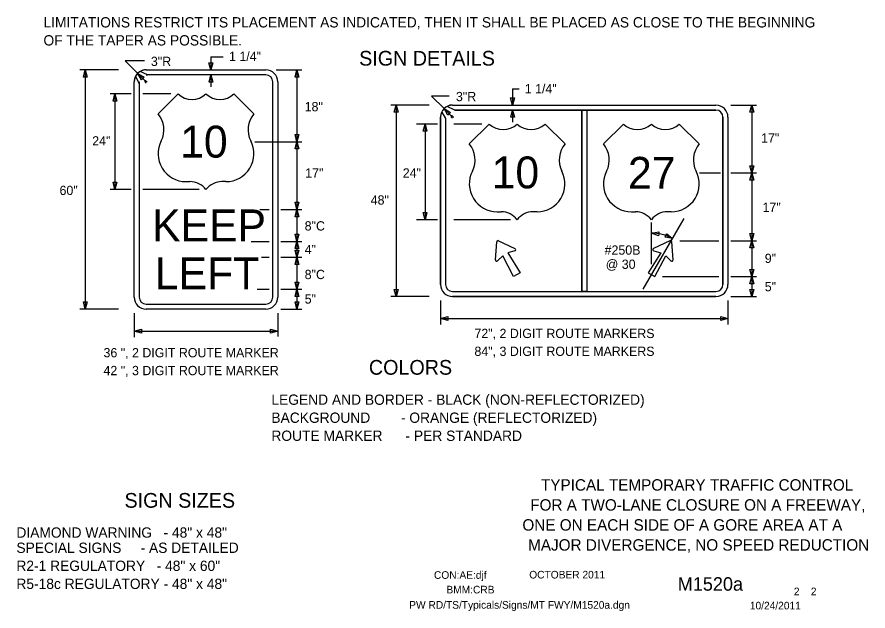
# Model space of a CAD drawing. Extents: x 16731 to 18475, y 7005 to 8303.
# Drawn here: x 17780 to 18473, y 7218 to 7702 of the extents above; entities that cross this region are included whole.
import ezdxf

# ---------------------------------------------------------------- set-up
doc = ezdxf.new("R2010")
doc.units = 0
for name, color, linetype in [('BORDER', 7, 'Continuous'), ('BORDER_SIGNAL_WO', 7, 'Continuous'), ('TRAFFIC_SIGNS_PR', 7, 'Continuous'), ('TYPICAL_EX', 7, 'Continuous'), ('TYPICAL_TEXT_DIMEN_PR', 7, 'Continuous')]:
    doc.layers.add(name, color=color, linetype=linetype)

msp = doc.modelspace()

# ---------------------------------------------------------------- linework, layer by layer
at = {"layer": 'BORDER'}
msp.add_line((17909.25, 7314.23), (17909.25, 7314.23), dxfattribs=at)
at = {"layer": 'TRAFFIC_SIGNS_PR'}
for p, q in [((17886.5, 7654.99), (17880.4, 7657.74)), ((17885.3, 7659.06), (17982.8, 7659.06)), ((17877.72, 7655.44), (17876.71, 7653.93)), ((17876.74, 7653.86), (17879.61, 7647.82)), ((17982.8, 7654.99), (17885.3, 7654.99)), ((17875.55, 7473.81), (17875.55, 7649.31)), ((17879.61, 7649.31), (17879.61, 7473.81)), ((17988.48, 7473.81), (17988.48, 7649.31)), ((17992.55, 7649.31), (17992.55, 7473.81)), ((18134.82, 7630.36), (18349.32, 7630.36)), ((18134.82, 7630.36), (18349.32, 7630.36)), ((18125.99, 7624.62), (18129.12, 7619.57)), ((18136.77, 7626.31), (18130.54, 7629.32)), ((18136.76, 7626.3), (18240.04, 7626.3)), ((18349.32, 7626.3), (18136.76, 7626.3)), ((18240.04, 7626.3), (18240.04, 7478.42)), ((18244.1, 7626.3), (18244.1, 7478.42)), ((18244.1, 7626.3), (18349.32, 7626.3)), ((18125.07, 7620.61), (18125.07, 7484.11)), ((18125.07, 7484.11), (18125.07, 7620.61)), ((18129.13, 7619.56), (18129.13, 7484.11)), ((18129.13, 7619.56), (18129.13, 7484.11)), ((18355.01, 7620.61), (18355.01, 7574.86)), ((18355.01, 7484.11), (18355.01, 7620.61)), ((18359.07, 7620.61), (18359.07, 7484.11)), ((18359.07, 7620.61), (18359.07, 7484.11)), ((18355.01, 7574.86), (18355.01, 7484.11)), ((18169.67, 7504.22), (18170.82, 7518.93)), ((18172.33, 7519.8), (18185.65, 7513.44)), ((18311.8, 7519.8), (18298.49, 7513.44)), ((18314.47, 7504.22), (18313.31, 7518.93)), ((18134.82, 7478.42), (18349.32, 7478.42)), ((18134.82, 7474.36), (18349.32, 7474.36)), ((18349.32, 7474.36), (18134.82, 7474.36)), ((17885.3, 7468.12), (17982.8, 7468.12)), ((17982.8, 7464.06), (17885.3, 7464.06))]:
    msp.add_line(p, q, dxfattribs=at)
for points in [[(18136.76, 7626.3), (18136.74, 7626.3)], [(18129.12, 7619.57), (18129.13, 7619.56)], [(18185.49, 7511.47), (18179.76, 7509.9), (18189.98, 7493.73), (18184.58, 7490.61), (18175.69, 7507.54), (18171.46, 7503.38)], [(18298.65, 7511.47), (18304.37, 7509.9), (18294.16, 7493.73), (18299.55, 7490.61), (18308.45, 7507.54), (18312.67, 7503.38)]]:
    msp.add_lwpolyline(points, dxfattribs=at)
msp.add_lwpolyline([(18240.04, 7626.3), (18244.1, 7626.3), (18244.1, 7478.42), (18240.04, 7478.42)], close=True, dxfattribs=at)
for centre, radius, start, end in [((17885.3, 7649.31), 9.75, 90, 180), ((17884.71, 7651.48), 7.6, 85.58319, 124.53531), ((17982.8, 7649.31), 9.75, 0, 90), ((17882.58, 7649.9), 7.06, 145.86811, 184.82317), ((17885.9, 7659.42), 4.47, 262.2432, 277.7568), ((17982.8, 7649.31), 5.69, 0, 90), ((17874.15, 7648.56), 5.51, 352.24294, 7.75653), ((18134.82, 7620.61), 9.75, 90, 180), ((18134.82, 7620.61), 9.75, 90, 180), ((18134.14, 7623.79), 6.6, 84.11162, 123.06374), ((18349.32, 7620.61), 9.75, 0, 90), ((18349.32, 7620.61), 9.75, 0, 90), ((18131.2, 7621.31), 6.17, 147.60925, 186.56283), ((18135.76, 7633.48), 7.24, 277.81035, 278.05403), ((18349.32, 7620.61), 5.69, 0, 89.99421), ((18349.32, 7620.61), 5.69, 0, 90), ((18171.88, 7518.85), 1.06, 64.48226, 175.51774), ((18312.26, 7518.85), 1.06, 4.48226, 115.51774), ((18185.19, 7512.49), 1.06, 285.9885, 64.48226), ((18298.94, 7512.49), 1.06, 115.51774, 254.0115), ((18170.73, 7504.14), 1.06, 175.51775, 314.01151), ((18313.41, 7504.14), 1.06, 225.98849, 4.48225), ((18134.82, 7484.11), 9.75, 180, 270), ((18134.82, 7484.11), 9.75, 180, 270), ((18134.82, 7484.11), 5.69, 180, 270), ((18134.82, 7484.11), 5.69, 180, 270), ((18349.32, 7484.11), 9.75, 270, 0), ((18349.32, 7484.11), 5.69, 270, 0), ((18349.32, 7484.11), 9.75, 270, 0), ((18349.32, 7484.11), 5.69, 270, 0), ((17885.3, 7473.81), 9.75, 180, 270), ((17885.3, 7473.81), 5.69, 180, 270), ((17982.8, 7473.81), 5.69, 270, 0), ((17982.8, 7473.81), 9.75, 270, 0)]:
    msp.add_arc(centre, radius, start, end, dxfattribs=at)
at = {"layer": 'TYPICAL_EX'}
for p, q in [((17895.05, 7623.31), (17911.3, 7639.56)), ((17973.05, 7623.31), (17956.8, 7639.56)), ((18148.43, 7598.7), (18164.68, 7614.95)), ((18226.43, 7598.7), (18210.18, 7614.95)), ((18257.71, 7598.7), (18273.96, 7614.95)), ((18335.71, 7598.7), (18319.46, 7614.95)), ((17917.77, 7568.02), (17921.02, 7568.02)), ((17950.32, 7568.02), (17947.07, 7568.02)), ((18171.16, 7543.41), (18174.41, 7543.41)), ((18203.7, 7543.41), (18200.45, 7543.41)), ((18280.43, 7543.41), (18283.68, 7543.41)), ((18312.98, 7543.41), (18309.73, 7543.41))]:
    msp.add_line(p, q, dxfattribs=at)
for centre, radius, start, end in [((17922.67, 7651.39), 16.42, 226.14041, 313.85958), ((17945.42, 7651.39), 16.42, 226.14042, 313.85959), ((17879.65, 7610.29), 20.16, 333.09768, 40.19361), ((17988.45, 7610.29), 20.16, 139.80639, 206.90233), ((18176.06, 7626.78), 16.42, 226.14041, 313.85958), ((18198.8, 7626.78), 16.42, 226.14042, 313.85959), ((18285.33, 7626.78), 16.42, 226.14041, 313.85958), ((18308.08, 7626.78), 16.42, 226.14042, 313.85959), ((17917.81, 7590.74), 22.73, 152.6698, 269.90132), ((17950.28, 7590.74), 22.73, 270.09868, 27.3302), ((18133.03, 7585.68), 20.16, 333.09768, 40.19361), ((18241.83, 7585.68), 20.16, 139.80639, 206.90233), ((18242.31, 7585.68), 20.16, 333.09768, 40.19361), ((18351.11, 7585.68), 20.16, 139.80639, 206.90233), ((18171.2, 7566.13), 22.73, 152.6698, 269.90132), ((18203.66, 7566.13), 22.73, 270.09868, 27.3302), ((18280.48, 7566.13), 22.73, 152.6698, 269.90132), ((18312.94, 7566.13), 22.73, 270.09868, 27.3302), ((17921.06, 7551.74), 16.28, 37.1038, 90.13853), ((17947.03, 7551.74), 16.28, 89.86147, 142.8962), ((18174.45, 7527.13), 16.28, 37.1038, 90.13853), ((18200.41, 7527.13), 16.28, 89.86147, 142.8962), ((18283.73, 7527.13), 16.28, 37.1038, 90.13853), ((18309.69, 7527.13), 16.28, 89.86147, 142.8962)]:
    msp.add_arc(centre, radius, start, end, dxfattribs=at)
at = {"layer": 'TYPICAL_TEXT_DIMEN_PR'}
for p, q in [((17883.92, 7666.34), (17868.26, 7666.34)), ((17868.26, 7666.34), (17878.5, 7656.1)), ((17938.02, 7659.06), (17936.45, 7664.92)), ((17936.45, 7664.92), (17938.02, 7664.92)), ((17938.02, 7669.82), (17938.02, 7659.06)), ((17938.02, 7669.82), (17948.12, 7669.82)), ((17938.02, 7664.92), (17939.59, 7664.92)), ((17939.59, 7664.92), (17938.02, 7659.06)), ((17862.72, 7659.06), (17831.42, 7659.06)), ((17834.19, 7653.19), (17835.76, 7659.06)), ((17835.76, 7659.06), (17835.76, 7464.06)), ((17835.76, 7659.06), (17837.33, 7653.19)), ((17991.09, 7659.06), (18012.05, 7659.06)), ((18006.58, 7653.19), (18008.15, 7659.06)), ((18008.15, 7659.06), (18008.15, 7600.56)), ((18008.15, 7659.06), (18009.72, 7653.19)), ((17835.76, 7653.19), (17834.19, 7653.19)), ((17837.33, 7653.19), (17835.76, 7653.19)), ((17878.5, 7656.1), (17885.06, 7649.55)), ((17881.53, 7650.85), (17878.5, 7656.1)), ((17878.5, 7656.1), (17883.75, 7653.07)), ((17882.64, 7651.96), (17881.53, 7650.85)), ((17883.75, 7653.07), (17882.64, 7651.96)), ((17885.06, 7648.34), (17885.06, 7650.76)), ((17936.5, 7649.13), (17938.07, 7654.99)), ((17938.07, 7654.99), (17938.07, 7645.24)), ((17938.07, 7654.99), (17939.64, 7649.13)), ((18008.15, 7653.19), (18006.58, 7653.19)), ((18009.72, 7653.19), (18008.15, 7653.19)), ((17883.85, 7649.55), (17886.26, 7649.55)), ((17938.07, 7649.13), (17936.5, 7649.13)), ((17939.64, 7649.13), (17938.07, 7649.13)), ((18183.67, 7643.51), (18183.67, 7630.36)), ((18183.67, 7643.51), (18189.2, 7643.51)), ((17873.17, 7639.56), (17856.05, 7639.56)), ((17858.37, 7633.69), (17859.94, 7639.56)), ((17859.94, 7639.56), (17859.94, 7561.56)), ((17859.94, 7639.56), (17861.51, 7633.69)), ((17905.41, 7639.56), (17882.54, 7639.56)), ((18131.96, 7637.64), (18117.78, 7637.64)), ((18117.78, 7637.64), (18127.93, 7627.49)), ((17859.94, 7633.69), (17858.37, 7633.69)), ((17861.51, 7633.69), (17859.94, 7633.69)), ((18115.83, 7630.36), (18084.54, 7630.36)), ((18087.31, 7624.5), (18088.88, 7630.36)), ((18088.88, 7630.36), (18088.88, 7474.36)), ((18088.88, 7630.36), (18090.45, 7624.5)), ((18183.68, 7630.36), (18182.1, 7636.22)), ((18182.1, 7636.22), (18183.68, 7636.22)), ((18183.68, 7636.22), (18185.25, 7636.22)), ((18185.25, 7636.22), (18183.68, 7630.36)), ((18361.44, 7630.36), (18382.4, 7630.36)), ((18376.93, 7624.5), (18378.5, 7630.36)), ((18378.5, 7630.36), (18378.5, 7575.11)), ((18378.5, 7630.36), (18380.08, 7624.5)), ((18088.88, 7624.5), (18087.31, 7624.5)), ((18090.45, 7624.5), (18088.88, 7624.5)), ((18127.93, 7627.49), (18134.58, 7620.85)), ((18130.97, 7622.24), (18127.93, 7627.49)), ((18127.93, 7627.49), (18133.19, 7624.46)), ((18132.08, 7623.35), (18130.97, 7622.24)), ((18133.19, 7624.46), (18132.08, 7623.35)), ((18182.15, 7620.43), (18183.73, 7626.3)), ((18182.15, 7620.43), (18183.73, 7626.3)), ((18183.72, 7626.3), (18183.72, 7616.55)), ((18183.73, 7626.3), (18185.3, 7620.43)), ((18183.73, 7626.3), (18185.3, 7620.43)), ((18378.5, 7624.5), (18376.93, 7624.5)), ((18380.08, 7624.5), (18378.5, 7624.5)), ((18133.37, 7620.85), (18135.79, 7620.85)), ((18134.58, 7619.64), (18134.58, 7622.06)), ((18183.73, 7620.43), (18182.15, 7620.43)), ((18183.73, 7620.43), (18182.15, 7620.43)), ((18185.3, 7620.43), (18183.73, 7620.43)), ((18185.3, 7620.43), (18183.73, 7620.43)), ((18122.69, 7614.95), (18105.57, 7614.95)), ((18110.87, 7609.08), (18112.44, 7614.95)), ((18112.44, 7609.08), (18110.87, 7609.08)), ((18112.44, 7614.95), (18112.44, 7536.95)), ((18112.44, 7614.95), (18114.01, 7609.08)), ((18114.01, 7609.08), (18112.44, 7609.08)), ((18158.8, 7614.95), (18135.92, 7614.95)), ((18008.15, 7600.56), (18006.58, 7606.42)), ((18006.58, 7606.42), (18008.15, 7606.42)), ((18008.15, 7606.42), (18009.72, 7606.42)), ((18009.72, 7606.42), (18008.15, 7600.56)), ((17973.94, 7600.56), (18012.05, 7600.56)), ((18006.58, 7594.69), (18008.15, 7600.56)), ((18008.15, 7600.56), (18008.15, 7545.31)), ((18008.15, 7600.56), (18009.72, 7594.69)), ((18008.15, 7594.69), (18006.58, 7594.69)), ((18009.72, 7594.69), (18008.15, 7594.69)), ((18378.5, 7575.11), (18376.93, 7580.97)), ((18376.93, 7580.97), (18378.5, 7580.97)), ((18378.5, 7580.97), (18380.08, 7580.97)), ((18380.08, 7580.97), (18378.5, 7575.11)), ((18335.88, 7575.11), (18353.03, 7575.11)), ((18361.44, 7575.11), (18382.4, 7575.11)), ((18376.93, 7569.25), (18378.5, 7575.11)), ((18378.5, 7575.11), (18378.5, 7519.86)), ((18378.5, 7575.11), (18380.08, 7569.25)), ((17859.94, 7561.56), (17858.37, 7567.42)), ((17858.37, 7567.42), (17859.94, 7567.42)), ((17859.94, 7567.42), (17861.51, 7567.42)), ((17861.51, 7567.42), (17859.94, 7561.56)), ((18378.5, 7569.25), (18376.93, 7569.25)), ((18380.08, 7569.25), (18378.5, 7569.25)), ((17873.17, 7561.56), (17856.05, 7561.56)), ((17928.54, 7561.56), (17882.54, 7561.56)), ((18008.15, 7545.31), (18006.58, 7551.17)), ((18006.58, 7551.17), (18008.15, 7551.17)), ((18008.15, 7551.17), (18009.72, 7551.17)), ((18009.72, 7551.17), (18008.15, 7545.31)), ((17977.88, 7545.31), (17985.56, 7545.31)), ((17994.92, 7545.31), (18012.05, 7545.31)), ((18006.58, 7539.44), (18008.15, 7545.31)), ((18008.15, 7539.44), (18006.58, 7539.44)), ((18008.15, 7545.31), (18008.15, 7519.31)), ((18008.15, 7545.31), (18009.72, 7539.44)), ((18009.72, 7539.44), (18008.15, 7539.44)), ((18112.44, 7536.95), (18110.87, 7542.81)), ((18110.87, 7542.81), (18112.44, 7542.81)), ((18112.44, 7542.81), (18114.01, 7542.81)), ((18114.01, 7542.81), (18112.44, 7536.95)), ((18122.69, 7536.95), (18105.57, 7536.95)), ((18181.92, 7536.95), (18135.92, 7536.95)), ((18290.1, 7480.46), (18323.34, 7538.05)), ((18296.86, 7500.61), (18296.86, 7534.6)), ((18296.89, 7526.05), (18302.88, 7527.01)), ((18302.56, 7523.89), (18296.89, 7526.05)), ((18302.88, 7527.01), (18302.72, 7525.45)), ((18308.56, 7524.14), (18309.24, 7525.56)), ((18309.24, 7525.56), (18313.84, 7521.6)), ((18378.5, 7519.86), (18376.93, 7525.72)), ((18376.93, 7525.72), (18378.5, 7525.72)), ((18378.5, 7525.72), (18380.08, 7525.72)), ((18380.08, 7525.72), (18378.5, 7519.86)), ((17970.86, 7519.31), (17985.56, 7519.31)), ((17994.92, 7519.31), (18012.05, 7519.31)), ((18008.15, 7519.31), (18006.58, 7525.17)), ((18006.58, 7525.17), (18008.15, 7525.17)), ((18006.58, 7513.44), (18008.15, 7519.31)), ((18008.15, 7525.17), (18009.72, 7525.17)), ((18009.72, 7525.17), (18008.15, 7519.31)), ((18008.15, 7519.31), (18008.15, 7506.31)), ((18008.15, 7519.31), (18009.72, 7513.44)), ((18302.72, 7525.45), (18302.56, 7523.89)), ((18307.87, 7522.73), (18308.56, 7524.14)), ((18313.84, 7521.6), (18307.87, 7522.73)), ((18319.81, 7519.86), (18351.68, 7519.86)), ((18361.44, 7519.86), (18382.4, 7519.86)), ((18376.93, 7514), (18378.5, 7519.86)), ((18378.5, 7519.86), (18378.5, 7490.61)), ((18378.5, 7519.86), (18380.08, 7514)), ((18008.15, 7513.44), (18006.58, 7513.44)), ((18008.15, 7506.31), (18006.58, 7512.17)), ((18006.58, 7512.17), (18008.15, 7512.17)), ((18009.72, 7513.44), (18008.15, 7513.44)), ((18008.15, 7512.17), (18009.72, 7512.17)), ((18009.72, 7512.17), (18008.15, 7506.31)), ((18378.5, 7514), (18376.93, 7514)), ((18380.08, 7514), (18378.5, 7514)), ((17979.21, 7506.31), (17985.56, 7506.31)), ((17994.92, 7506.31), (18012.05, 7506.31)), ((18006.58, 7500.44), (18008.15, 7506.31)), ((18008.15, 7506.31), (18008.15, 7480.31)), ((18008.15, 7506.31), (18009.72, 7500.44)), ((18008.15, 7500.44), (18006.58, 7500.44)), ((18009.72, 7500.44), (18008.15, 7500.44)), ((18378.5, 7490.61), (18376.93, 7496.47)), ((18376.93, 7496.47), (18378.5, 7496.47)), ((18378.5, 7496.47), (18380.08, 7496.47)), ((18380.08, 7496.47), (18378.5, 7490.61)), ((18008.15, 7480.31), (18006.58, 7486.17)), ((18006.58, 7486.17), (18008.15, 7486.17)), ((18008.15, 7486.17), (18009.72, 7486.17)), ((18009.72, 7486.17), (18008.15, 7480.31)), ((18305.67, 7490.61), (18351.68, 7490.61)), ((18361.44, 7490.61), (18382.4, 7490.61)), ((18376.93, 7484.75), (18378.5, 7490.61)), ((18378.5, 7484.75), (18376.93, 7484.75)), ((18378.5, 7490.61), (18378.5, 7474.36)), ((18378.5, 7490.61), (18380.08, 7484.75)), ((18380.08, 7484.75), (18378.5, 7484.75)), ((17975.71, 7480.31), (17985.56, 7480.31)), ((17994.92, 7480.31), (18012.05, 7480.31)), ((18006.58, 7474.44), (18008.15, 7480.31)), ((18008.15, 7480.31), (18008.15, 7464.06)), ((18008.15, 7480.31), (18009.72, 7474.44)), ((18088.88, 7474.36), (18087.31, 7480.22)), ((18087.31, 7480.22), (18088.88, 7480.22)), ((18088.88, 7480.22), (18090.45, 7480.22)), ((18090.45, 7480.22), (18088.88, 7474.36)), ((18378.5, 7474.36), (18376.93, 7480.22)), ((18376.93, 7480.22), (18378.5, 7480.22)), ((18378.5, 7480.22), (18380.08, 7480.22)), ((18380.08, 7480.22), (18378.5, 7474.36)), ((18008.15, 7474.44), (18006.58, 7474.44)), ((18009.72, 7474.44), (18008.15, 7474.44)), ((18115.83, 7474.36), (18084.54, 7474.36)), ((18125.07, 7471.01), (18125.07, 7451.45)), ((18359.07, 7471.01), (18359.07, 7451.45)), ((18361.44, 7474.36), (18378.57, 7474.36)), ((18361.44, 7474.36), (18382.4, 7474.36)), ((18361.44, 7474.36), (18378.57, 7474.36)), ((17862.72, 7464.06), (17831.42, 7464.06)), ((17835.76, 7464.06), (17834.19, 7469.92)), ((17834.19, 7469.92), (17835.76, 7469.92)), ((17835.76, 7469.92), (17837.33, 7469.92)), ((17837.33, 7469.92), (17835.76, 7464.06)), ((17994.92, 7464.06), (18012.05, 7464.06)), ((18008.15, 7464.06), (18006.58, 7469.92)), ((18006.58, 7469.92), (18008.15, 7469.92)), ((18008.15, 7469.92), (18009.72, 7469.92)), ((18009.72, 7469.92), (18008.15, 7464.06)), ((17875.55, 7460.71), (17875.55, 7441.36)), ((17992.55, 7460.71), (17992.55, 7441.82)), ((18125.07, 7456.39), (18130.93, 7457.96)), ((18125.07, 7456.39), (18359.07, 7456.39)), ((18130.93, 7454.82), (18125.07, 7456.39)), ((18130.93, 7457.96), (18130.93, 7456.39)), ((18130.93, 7456.39), (18130.93, 7454.82)), ((18353.21, 7456.39), (18353.21, 7457.96)), ((18353.21, 7457.96), (18359.07, 7456.39)), ((18359.07, 7456.39), (18353.21, 7454.82)), ((18353.21, 7454.82), (18353.21, 7456.39)), ((17875.55, 7446.08), (17881.41, 7447.65)), ((17875.55, 7446.08), (17992.55, 7446.08)), ((17881.41, 7444.51), (17875.55, 7446.08)), ((17881.41, 7447.65), (17881.41, 7446.08)), ((17881.41, 7446.08), (17881.41, 7444.51)), ((17986.69, 7446.08), (17986.69, 7447.65)), ((17986.69, 7447.65), (17992.55, 7446.08)), ((17992.55, 7446.08), (17986.69, 7444.51)), ((17986.69, 7444.51), (17986.69, 7446.08))]:
    msp.add_line(p, q, dxfattribs=at)
msp.add_arc((18297.05, 7491.61), 34.39, 60.74521, 90.32117, dxfattribs=at)

# ---------------------------------------------------------------- texts
at = {"layer": 'BORDER'}
for s, p in [('TYPICAL TEMPORARY TRAFFIC CONTROL', (18206.86, 7316.18)), ('FOR A TWO-LANE CLOSURE ON A FREEWAY,', (18198.1, 7299.88)), ('ONE ON EACH SIDE OF A GORE AREA AT A ', (18191.71, 7283.58)), ('MAJOR DIVERGENCE, NO SPEED REDUCTION', (18196.36, 7267.28))]:
    msp.add_text(s, height=9.3, dxfattribs=at).set_placement(p)
at = {"layer": 'BORDER_SIGNAL_WO'}
for s, height, p in [('CON:AE:djf  ', 6.2, (18119.69, 7244.31)), ('    OCTOBER 2011    ', 6.2, (18188.08, 7244.59)), ('    M1520a   ', 11, (18301.86, 7234.63)), ('BMM:CRB   ', 6.2, (18129.81, 7232.42)), (' 2    2 ', 6.2, (18410.45, 7230.95)), ('PW RD/TS/Typicals/Signs/MT FWY/M1520a.dgn      ', 6.2, (18099.55, 7219.96)), ('10/24/2011    ', 6.2, (18376.93, 7219.38))]:
    msp.add_text(s, height=height, dxfattribs=at).set_placement(p)
at = {"layer": 'TRAFFIC_SIGNS_PR'}
for s, p in [('10', (17913.02, 7587.56)), ('10', (18166.67, 7562.49)), ('27', (18277.67, 7562.13)), ('KEEP', (17890.15, 7519.31)), ('LEFT', (17892.38, 7480.31))]:
    msp.add_text(s, height=26, dxfattribs=at).set_placement(p)
at = {"layer": 'TYPICAL_TEXT_DIMEN_PR'}
for s, height, p in [('LIMITATIONS RESTRICT ITS PLACEMENT AS INDICATED, THEN IT SHALL BE PLACED AS CLOSE TO THE BEGINNING', 8.4, (17801.7, 7693.62)), ('OF THE TAPER AS POSSIBLE.', 8.4, (17801.7, 7678.93)), ('1 1/4"', 7.55, (17952.82, 7666.31)), ('SIGN DETAILS', 12, (18058.77, 7662.53)), ('3"R', 7.55, (17889.19, 7662.22)), ('1 1/4"', 7.55, (18193.6, 7639.93)), ('3"R', 7.55, (18137.6, 7633.56)), ('18"', 7.55, (18014.39, 7625.32)), ('24"', 7.55, (17841.39, 7597.44)), ('17"', 7.55, (18386.08, 7599.72)), ('17"', 7.55, (18014.85, 7571.28)), ('24"', 7.55, (18094.29, 7571.28)), ('60"', 7.55, (17814.79, 7557.07)), ('48"', 7.55, (18068.18, 7549.26)), ('17"', 7.55, (18387.28, 7543.36)), ('8"C', 7.55, (18014.42, 7528.16)), ('4" ', 7.55, (18014.42, 7508.9)), ('#250B', 7.55, (18258.63, 7508.45)), ('@ 30', 7.55, (18259.57, 7496.9)), ('9"', 7.55, (18389.06, 7501.7)), ('8"C', 7.55, (18014.42, 7488.57)), ('5"', 7.55, (18389.06, 7478.6)), ('5" ', 7.55, (18014.42, 7468.6)), ('72", 2 DIGIT ROUTE MARKERS', 7.55, (18152.65, 7440.52)), ('36 ", 2 DIGIT ROUTE MARKER', 7.55, (17850.59, 7424.82)), ('84", 3 DIGIT ROUTE MARKERS', 7.55, (18152.65, 7425.97)), ('COLORS', 12, (18066.71, 7410.64)), ('42 ", 3 DIGIT ROUTE MARKER', 7.55, (17850.59, 7410.27)), ('LEGEND AND BORDER - BLACK (NON-REFLECTORIZED)', 8.4, (17987.29, 7386.11)), ('BACKGROUND        - ORANGE (REFLECTORIZED)', 8.4, (17987.29, 7371.41)), ('ROUTE MARKER      - PER STANDARD', 8.4, (17987.29, 7356.71)), ('SIGN SIZES', 12, (17867.69, 7302.23)), ('DIAMOND WARNING   - 48" x 48"', 8.4, (17779.65, 7277.83)), ('SPECIAL SIGNS     - AS DETAILED', 8.4, (17779.65, 7265.43)), ('R2-1 REGULATORY   - 48" x 60"', 8.4, (17779.65, 7250.73)), ('R5-18c REGULATORY - 48" x 48"', 8.4, (17779.65, 7236.03))]:
    msp.add_text(s, height=height, dxfattribs=at).set_placement(p)

doc.saveas('drawing.dxf')
